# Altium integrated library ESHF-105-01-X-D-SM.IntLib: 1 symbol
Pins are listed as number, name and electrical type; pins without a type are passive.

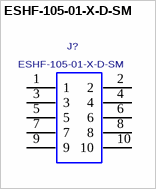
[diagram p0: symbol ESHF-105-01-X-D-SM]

## ESHF-105-01-X-D-SM
designator J?
0.05"X0.05" EXTRA LENGTH SHROUDED TERMINAL STRIP.; MANUFACTURER: SAMTEC
footprint ESHF-105-01-X-D-SM
pins: 1, 2, 3, 4, 5, 6, 7, 8, 9, 10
